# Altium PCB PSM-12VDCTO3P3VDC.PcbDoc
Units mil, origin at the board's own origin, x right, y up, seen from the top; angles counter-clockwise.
Board outline 8000 x 5800 mil, 2 copper layers (Top Layer, Bottom Layer), stack 62 mil thick; 35 components, 17 nets, 92 pads, 15 vias.
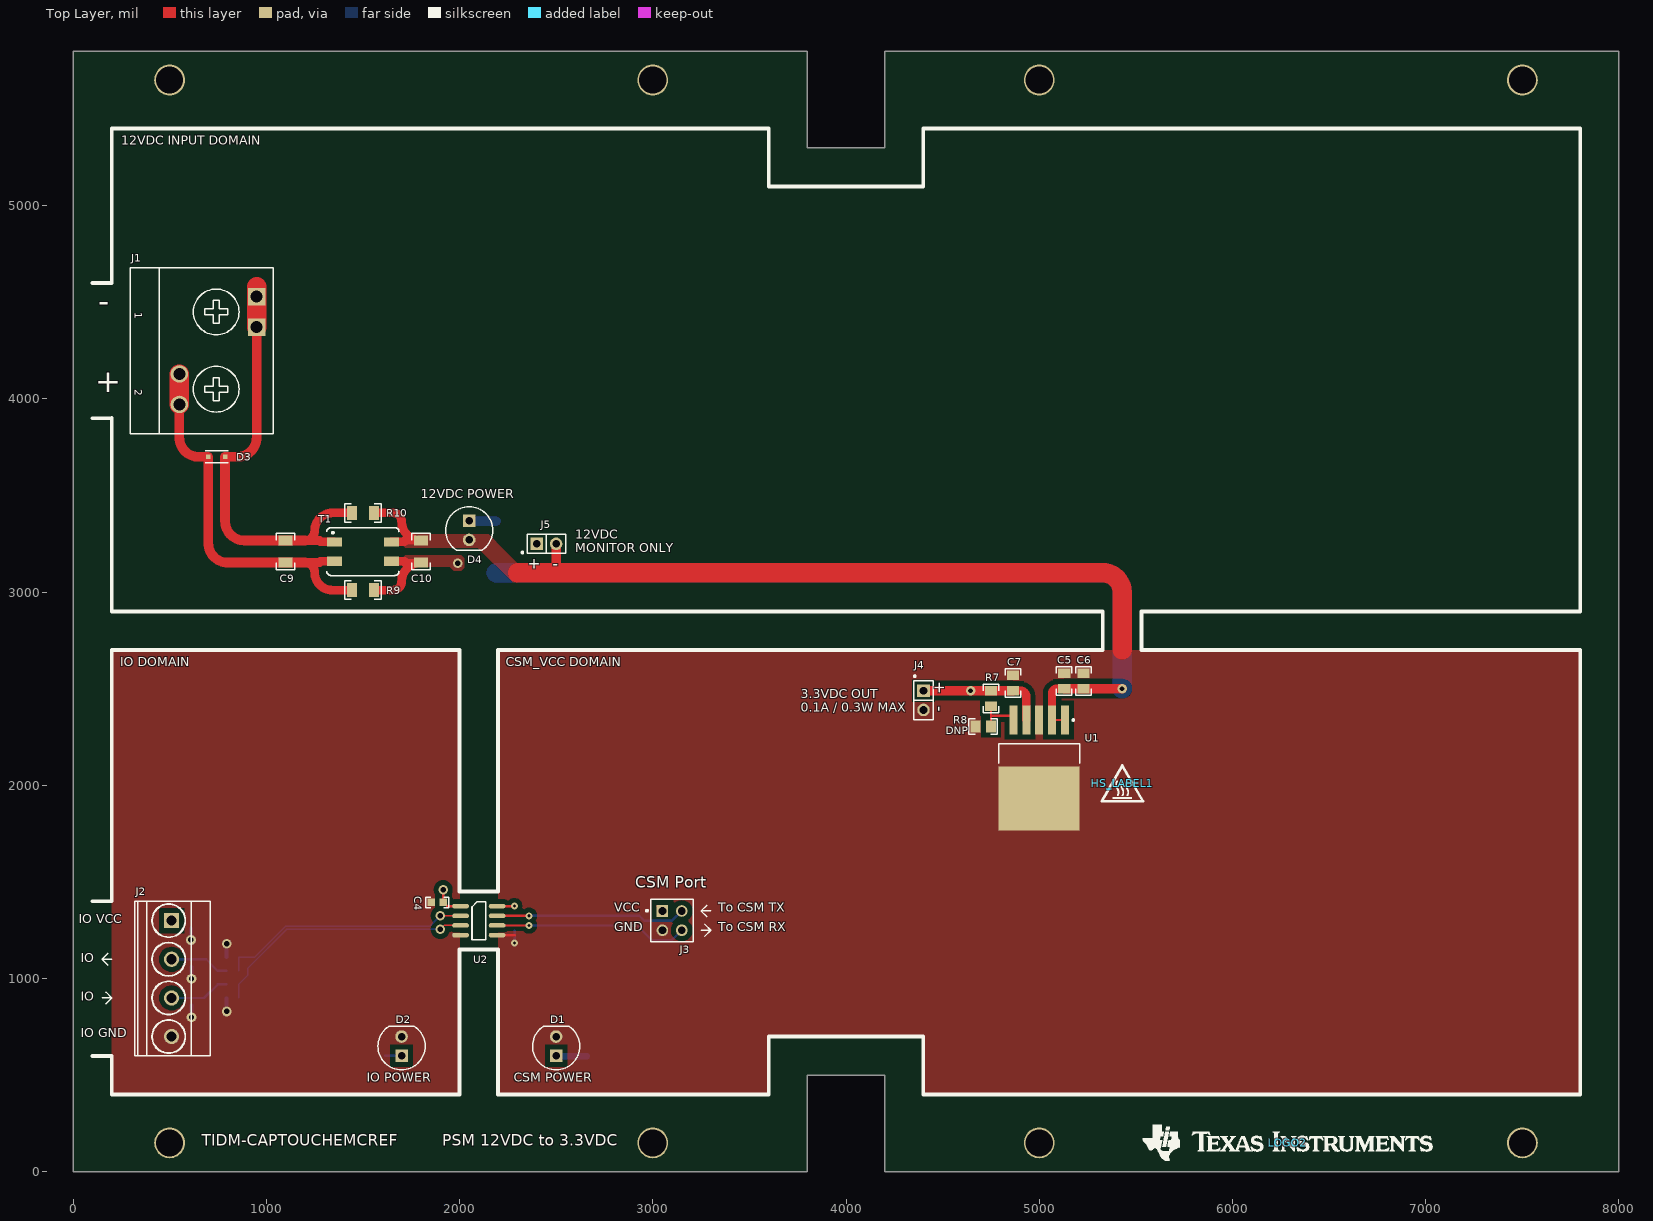
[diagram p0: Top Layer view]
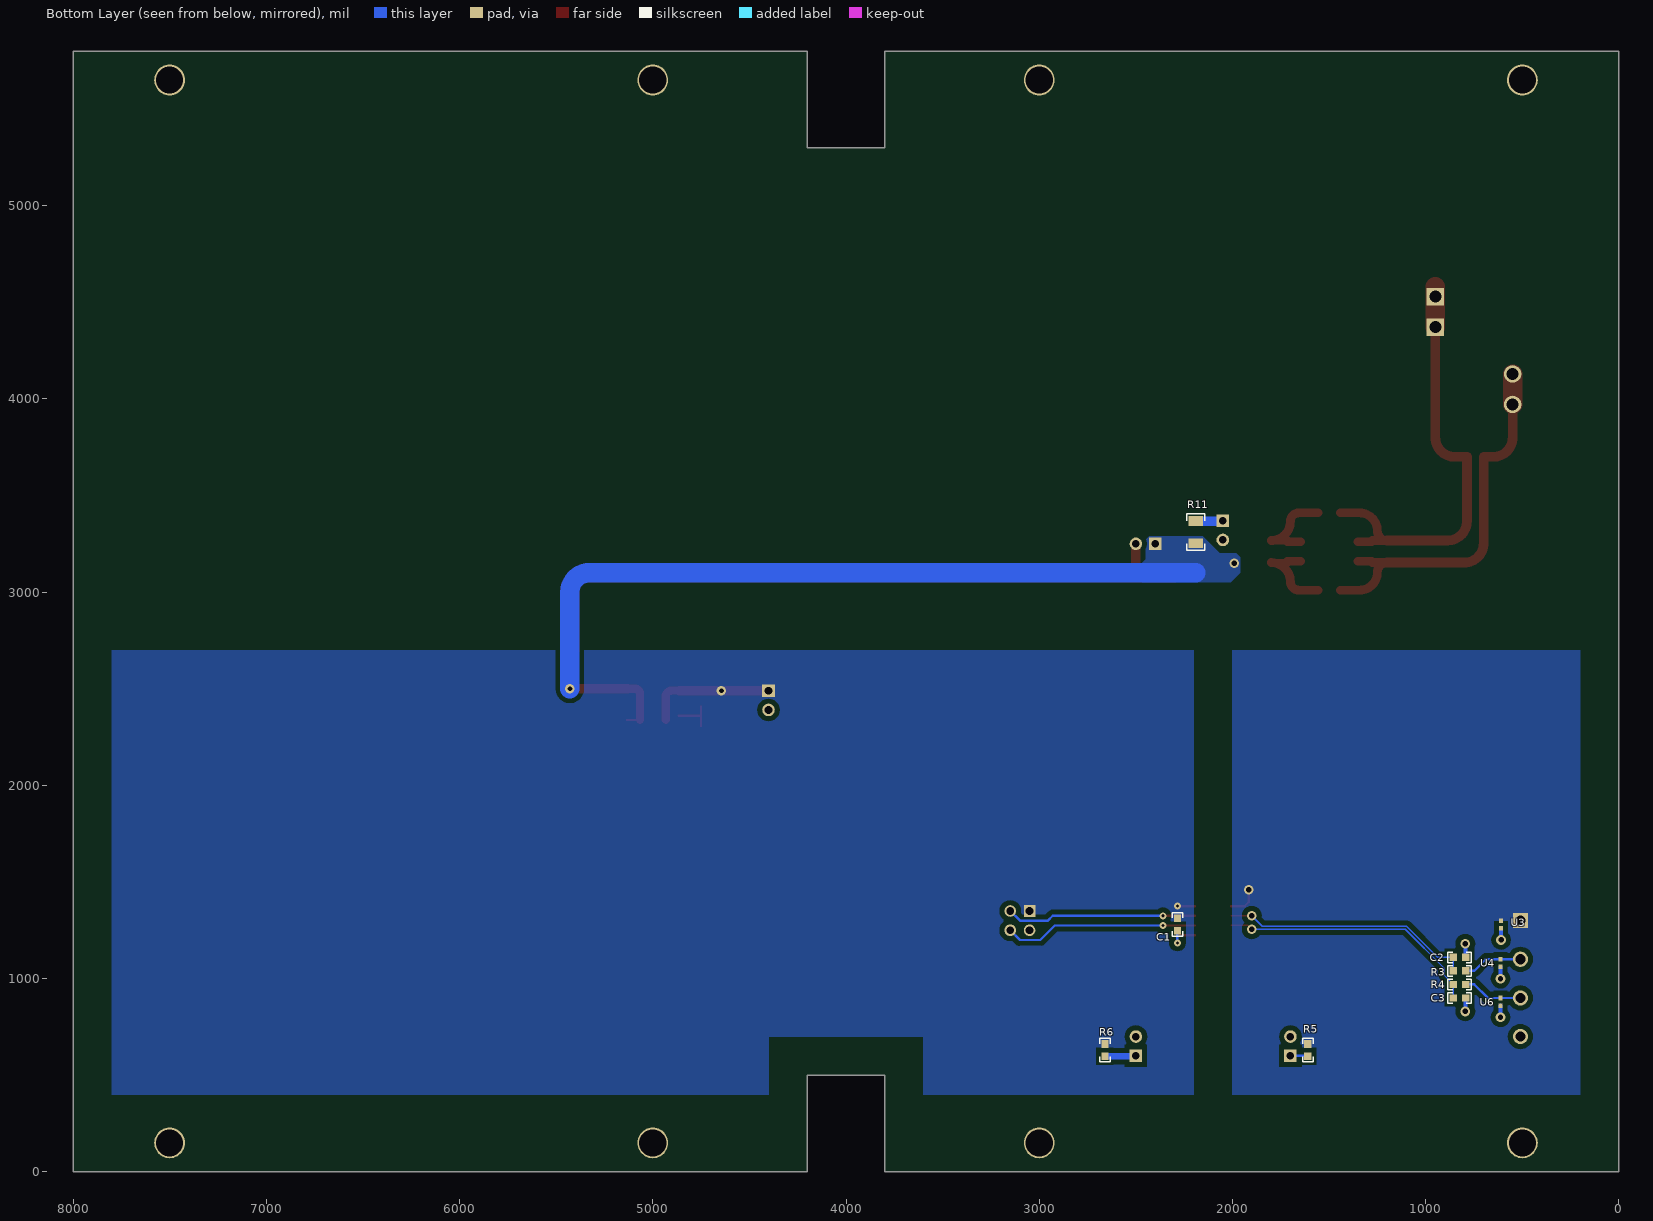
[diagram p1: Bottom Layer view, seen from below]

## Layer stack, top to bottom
Top Solder: solder mask 0.4, Solder Resist, Dk 3.5
Top Layer: signal copper 1.4
Dielectric1: core 59.2, FR-4, Dk 4.8
Bottom Layer: signal copper 1.4
Bottom Solder: solder mask 0.4, Solder Resist, Dk 3.5

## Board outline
0,0 0,5800 3800,5800 3800,5300 4200,5300 4200,5800 8000,5800 8000,0 4200,0 4200,500 3800,500 3800,0

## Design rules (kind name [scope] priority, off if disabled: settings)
AcuteAngle [All] p1: minimum=4.50000000000000E+0001 checktracksonly=FALSE
AssemblyTestPointUsage [All] p1: valid=2
Clearance Clearance_Keepouts [((IsTrack Or IsArc) And Not InPoly) And IsFree and IsKeepOut vs ((IsTrack Or IsArc) And Not InPoly) And IsFree and IsKeepOut] p1: gap=0
Clearance Clearance_BoardEdge_MountingHoles [OnCopper and InComponentClass('Mounting Holes') vs IsKeepOut] p2: gap=40
Clearance Clearance_BoardEdge_Poly [OnCopper and InPoly vs IsKeepOut] p3: gap=25
Clearance Clearance_BoardEdge [OnCopper and Not InComponentClass('Logo') and not InComponentClass('FiducialMark') and not InRegion(1000,500,4000,800) and Not IsKeepout vs IsKeepOut] p4: gap=75
Clearance Clearance_Poly [InPolygon] p5: gap=25
Clearance [All] p6: gap=7.87
ComponentClearance ComponentClearance_MountingHoles_FiducialMarks [InComponentClass('Mounting Holes') vs InComponentClass('FiducialMark')] p1: gap=50 collisioncheckmode=3 verticalgap=10 showdistances=FALSE
ComponentClearance ComponentClearance_Shunt [InComponentClass('Header') vs InComponentClass('Shunt')] p2: gap=0 collisioncheckmode=3 verticalgap=0 showdistances=FALSE
ComponentClearance ComponentClearance_Logo [InComponentClass('Logo')] p3: gap=50 collisioncheckmode=3 verticalgap=10 showdistances=FALSE
ComponentClearance ComponentClearance_ScrewToNut [(HasFootprint('NY PMS 440 0025 PH')) vs (HasFootprint('Keystone_1902C'))] p4: gap=5 collisioncheckmode=3 verticalgap=10 showdistances=FALSE
ComponentClearance ComponentClearance_MountingHoles [InComponentClass('Mounting Holes')] p5: gap=250 collisioncheckmode=3 verticalgap=100000 showdistances=FALSE
ComponentClearance ComponentClearance_SmallPassives [HasFootprint('0201*') or HasFootprint('0402*') or HasFootprint('0508') or HasFootprint('0603*') or HasFootprint('0612') or HasFootprint('0805*') or HasFootprint('0815*') or HasFootprint('0830*') or HasFootprint('1206*') or HasFootprint('1210*') or HasFootprint('1808*') or HasFootprint('1812*') or HasFootprint('1825*') or HasFootprint('2010*') or HasFootprint('2220*') or HasFootprint('2225*') or HasFootprint('2512*') or HasFootprint('2728*') or HasFootprint('3518*') vs HasFootprint('0201*') or HasFootprint('0402*') or HasFootprint('0508') or HasFootprint('0603*') or HasFootprint('0612') or HasFootprint('0805*') or HasFootprint('0815*') or HasFootprint('0830*') or HasFootprint('1206*') or HasFootprint('1210*') or HasFootprint('1808*') or HasFootprint('1812*') or HasFootprint('1825*') or HasFootprint('2010*') or HasFootprint('2220*') or HasFootprint('2225*') or HasFootprint('2512*') or HasFootprint('2728*') or HasFootprint('3518*')] p6: gap=20 collisioncheckmode=3 verticalgap=10 showdistances=FALSE
ComponentClearance ComponentClearance_THtoSMT [IsThruComponent vs IsSMTComponent] p7: gap=25 collisioncheckmode=3 verticalgap=30 showdistances=FALSE
ComponentClearance ComponentClearance_THtoTH [IsThruComponent vs IsThruComponent] p8: gap=50 collisioncheckmode=3 verticalgap=30 showdistances=FALSE
ComponentClearance [All] p9: gap=40 collisioncheckmode=3 verticalgap=10 showdistances=FALSE
DiffPairsRouting [All] p1: maxlimit=100 minlimit=10 mostfreqgap=10 toplayer_minwidth=15 toplayer_maxwidth=15 toplayer_prefwidth=15 bottomlayer_minwidth=15 bottomlayer_maxwidth=15 bottomlayer_prefwidth=15 maxuncoupledlength=1000
FabricationTestPointUsage TestPointUsage [All] p1: valid=2 allowmultiple=FALSE
FabricationTestpoint Testpoint [All] p1: side=3 testpointundercomponent=TRUE minsize=40 maxsize=100 preferedsize=60 minholesize=0 maxholesize=40 preferedholesize=32 testpointgrid=1 allowsidetop=TRUE allowsidebottom=TRUE usegrid=TRUE gridtolerance=0.01
FanoutControl Fanout_LCC [IsLCC] p1: bgadir=Out bgaviamode=Centered fanoutstyle=Auto fanoutdirection=Alternating viagrid=1 // Fanout_LCC (Default Rule)
FanoutControl Fanout_BGA [IsBGA] p2: bgadir=Out bgaviamode=Centered fanoutstyle=Auto fanoutdirection=Alternating viagrid=1 // Fanout_BGA (Default Rule)
FanoutControl Fanout_Default [All] p4: bgadir=Out bgaviamode=Centered fanoutstyle=Auto fanoutdirection=Alternating viagrid=1 // Fanout_Default (Default Rule)
FanoutControl Fanout_Small [(CompPinCount < 5)] p5: bgadir=Out bgaviamode=Centered fanoutstyle=Auto fanoutdirection=OutThenIn viagrid=1 // Fanout_Small (Default Rule)
Height [All] p1: minheight=0 maxheight=1500 prefheight=500
HoleSize [All] p1: absolutevalues=TRUE maxlimit=251 minlimit=8 maxpercent=80.000 minpercent=20.000
MinimumAnnularRing MinimumAnnularRing_ThermalPadVias [IsVia and InAnyComponent] p1: minimumring=5.91
MinimumAnnularRing [All] p2: minimumring=8
MinimumSolderMaskSliver MinimumSolderMaskSliver_Logo [InComponentClass('Logo') vs InComponentClass('Logo')] p1: minsoldermaskwidth=0.7
MinimumSolderMaskSliver [All] p2: minsoldermaskwidth=3.94
PlaneConnect [All] p1: planeconnectstyle=Relief reliefexpansion=10 reliefentries=4 reliefconductorwidth=10 reliefairgap=10
PolygonConnect [All] p1: connectstyle=Direct reliefconductorwidth=10 reliefentries=4 polygonreliefangle="90 Angle" airgapwidth=10
RoutingVias ThermalPadVias [IsVia and InAnyComponent] p1: holewidth=7.87 width=19.68 viastyle="Through Hole" minholewidth=7.87 minwidth=19.68 maxholewidth=12.99 maxwidth=23.62
RoutingVias [All] p2: holewidth=16 width=34 viastyle="Through Hole" minholewidth=7.87 minwidth=26 maxholewidth=40 maxwidth=65
SilkToBoardRegionClearance [Not ((IsComment or IsDesignator) And (Hide <> 'False')) and not InRegion(1000,500,4000,800)] p1:
SilkToSilkClearance SilkToSilkClearance_Pb-FreeLogo [(HasFootprint('Pb-Free_Overlay_Medium') OR HasFootprint('Pb-Free_Overlay_Small')) vs (HasFootprint('Pb-Free_Overlay_Medium') OR HasFootprint('Pb-Free_Overlay_Small'))] p1: silktosilkclearance=0
SilkToSilkClearance [All] p2: silktosilkclearance=5
SilkToSolderMaskClearance "Silk to Solder Mask Opening" [All] p1: minsilkscreentomaskgap=1 clearancetoexposedcopper=FALSE
SolderMaskExpansion [All] p1: expansion=3
Width [All] p1: maxlimit=100 minlimit=6 preferedwidth=10 checkconnectedcopper=TRUE
14 further rules are at their usual default settings.

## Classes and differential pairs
component class Header: J3 J4 J5
component class Logo: LOGO2

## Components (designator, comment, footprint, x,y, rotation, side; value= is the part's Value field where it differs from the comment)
C1 "GRM188R71C104KA01D" 0603 2285,1280 r270 bottom
C2 "06031C102JAT2A" 0603 825,1110 r180 bottom
C3 "06031C102JAT2A" 0603 825,900 r180 bottom
C4 "GRM188R71C104KA01D" 0603 1885,1395 r180 top
C5 "C2012X5R1E106K125AB" 0805_HV 5129,2540 r90 top
C6 "08053C104KAT2A" 0805_HV 5229,2540 r90 top
C7 "C2012X5R1C226K125AC" 0805_HV 4864,2530 r90 top
C9 "12061C104KAT2A" 1206 1100,3210 r90 top
C10 "12063C105KAT2A" 1206 1800,3210 r90 top
D1 "HLMP-3519" HLMP-351_GREEN 2500,650 r90 top
D2 "HLMP-3519" HLMP-351_GREEN 1700,650 r90 top
D3 "CDSOD323-T15SC" SOD-323-Bi 743.31,3700.01 r180 top
D4 "HLMP-3519" HLMP-351_GREEN 2050,3320 r270 top
HS_LABEL1 "CAUTION HOT SURFACE" IEC_HotSurface_Small 5430,2010 r0 top
J1 "0399100102" CONN_399100102 750,4250 r270 top
J2 "39544-3004" MOLEX_39544-3004 510,1000 r270 top
J3 "PEC02DAAN" Sullins_PEC02DAAN 3100,1300 r0 top
J4 "HTSW-102-07-G-S" Samtec_HTSW-102-07-G-S 4401.01,2440.21 r270 top
J5 "HTSW-102-07-G-S" Samtec_HTSW-102-07-G-S 2450,3250 r0 top
LOGO2 "Texas Instruments" TI_Horizontal_Overlay_Medium 6285,150 r0 top
R3 "CRCW060351R0JNEA" 0603 825,1040 r0 bottom
R4 "CRCW060351R0JNEA" 0603 825,970 r0 bottom
R5 "CRCW0603120RJNEA" 0603 1610,630 r90 bottom
R6 "CRCW0603120RJNEA" 0603 2660,630 r90 bottom
R7 "CRCW08050000Z0EA" 0805_HV 4750,2450 r90 top
R8 "CRCW08050000Z0EA" 0805_HV 4710,2305 r0 top
R9 "CRCW12060000Z0EA" 1206 1500,3010 r0 top
R10 "CRCW12060000Z0EA" 1206 1500,3410 r0 top
R11 "CRCW12061K00JNEA" 1206 2190,3310 r270 bottom
T1 "SRF0905-472Y" SRF0905 1500,3210 r0 top
U1 "TPS7A4533KTTR" KTT0005A_N 5000,2090 r270 top
U2 "ISO7221CD" D0008A_N 2100,1300 r0 top
U3 "TPD1E10B06DPYR" DPY0002A 610,1280 r90 bottom
U4 "TPD1E10B06DPYR" DPY0002A 612.76,1080 r90 bottom
U6 "TPD1E10B06DPYR" DPY0002A 612.76,880 r90 bottom

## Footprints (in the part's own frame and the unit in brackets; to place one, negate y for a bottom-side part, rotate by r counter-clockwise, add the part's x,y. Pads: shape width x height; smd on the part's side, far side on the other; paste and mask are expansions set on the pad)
0603 [mm] "0603 from SM-752 data"
  rect 1x0.95 smd: 1(-0.8,0) 2(0.8,0)
  silkscreen extent -1.52,-0.69 1.52,0.69, body extent -0.87,-0.47 0.87,0.47, height 0.85
0805_HV [mil] "0805 with 30mil clearance between pads"
  rect 50x63 smd: 1(-40,0) 2(40,0)
  silkscreen extent -74,-40 74,40, body extent -43,-29 43,29, height 43
1206 [mm] "1206 from SM-752 data"
  rect 1.3x1.85 smd: 1(-1.45,0) 2(1.45,0)
  silkscreen extent -2.4,-1.21 2.4,1.21, body extent -1.7,-0.9 1.7,0.9, height 1.35
CONN_399100102 [mm] "Molex"
  rect 2.3x2.3 hole 1.587: 1(-7.085,5.08) 1A(-3.075,5.08)
  round 2.3 hole 1.587: 2(3.075,-5.08) 2A(7.085,-5.08)
  silkscreen extent -10.88,-11.53 10.96,7.27, body extent -10.88,-11.53 10.96,7.27, height 31.1
D0008A_N [mm] "SOIC, 8-Leads, Body 4.9x3.9mm, Pitch 1.27mm, IPC Medium Density"
  oval 2.2x0.6 smd: 1(-2.4,1.905) 2(-2.4,0.635) 3(-2.4,-0.635) 4(-2.4,-1.905) 5(2.4,-1.905) 6(2.4,-0.635) 7(2.4,0.635) 8(2.4,1.905)
  silkscreen extent -0.9,-2.5 0.9,2.5, body extent -3,-2.45 3,2.45, height 1.63
DPY0002A [mm] "R-PX2SON-N2"
  rect 0.6x0.5 smd: 1(-0.5,0) 2(0.5,0)
  body extent -0.55,-0.35 0.55,0.35, height 0.4
HLMP-351_GREEN [mm] "AVAGO"
  rect 1.65x1.65 hole 1: 1(-1.27,0)
  round 1.65 hole 1: 2(1.27,0)
  silkscreen extent -3.1,-3.1 2.6,3.1, body extent -3.05,-3.06 2.57,3.06, height 10.78
IEC_HotSurface_Small [mil]
  silkscreen extent -107,-93 107,92
KTT0005A_N [mm] "D2-PAK, 6-Leads, Body 8.9x10.2mm, Pitch 1.7mm, Lead Span 15.2mm, IPC Medium Density"
  rect 3.8x1.05 smd: 1(-6.3,3.4) 2(-6.3,1.7) 3(-6.3,0) 4(-6.3,-1.7) 5(-6.3,-3.4)
  rect 8.4x10.65 smd: 6(4,0)
  silkscreen extent -6.42,-5.35 -0.65,5.35, body extent -3.2,-5.32 6.45,5.33, height 4.83
MOLEX_39544-3004 [mm] "Molex"
  rect 2x2 hole 1.321: 1(-7.62,0)
  round 2 hole 1.321: 2(-2.54,0) 3(2.54,0) 4(7.62,0)
  silkscreen extent -10.16,-4.83 10.16,5.08, body extent -10.16,-4.83 10.16,5.08, height 14.49
Samtec_HTSW-102-07-G-S [mm] "Samtec 100mil, 1x2, 230 mil above insulator"
  rect 1.65x1.65 hole 1.016 mask+0: 1(-1.27,0)
  round 1.65 hole 1.016 mask+0: 2(1.27,0)
  silkscreen extent -3.3,-1.27 2.54,1.27, body extent -2.54,-1.27 2.54,1.27, height 8.38
SOD-323-Bi [mm] "SOD323, 2-Leads, Body 1.9x1.45mm, No Polarity Mark"
  rect 0.6x0.6 smd paste-0.05: 1(-1.1,0) 2(1.1,0)
  silkscreen extent -1.53,-0.77 1.53,0.77, body extent -1.27,-0.65 1.27,0.65, height 1.02
SRF0905 [mm] "Bourns SRF0905 series recommended land pattern"
  rect 2x1.2 smd: 1(-3.75,1.27) 2(-3.75,-1.27) 3(3.75,-1.27) 4(3.75,1.27)
  silkscreen extent -4.75,-3.15 4.75,3.15, body extent -4.75,-3.15 4.75,3.15, height 5.3
Sullins_PEC02DAAN [mil] "Sullins Connector Solutions"
  rect 60x60 hole 40: 1(-50,50)
  round 60 hole 40: 2(50,50) 3(-50,-50) 4(50,-50)
  silkscreen extent -134,-110 110,110, body extent -110,-110 110,110, height 310
TI_Horizontal_Overlay_Medium [mil]
  silkscreen extent -750,-94 750,94

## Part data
C1 C4: "CAP, CERM, 0.1 µF, 16 V, +/- 10%, X7R, 0603"
C2 C3: "CAP, CERM, 1000 pF, 100 V, +/- 5%, X7R, 0603"
C5: "CAP, CERM, 10 µF, 25 V, +/- 10%, X5R, 0805"
C6: "CAP, CERM, 0.1 µF, 25 V, +/- 10%, X7R, 0805"
C7: "CAP, CERM, 22 µF, 16 V, +/- 10%, X5R, 0805"
C9: "CAP, CERM, 0.1 µF, 100 V, +/- 10%, X7R, 1206"
C10: "CAP, CERM, 1 µF, 25 V, +/- 10%, X7R, 1206"
D1 D2 D4: "LED, Green, TH"
D3: "Diode, TVS, Bi, 15 V, 400 W, SOD323, 2-Leads, Body 1.9x1.45mm, No Polarity Mark"
HS_LABEL1: library part IEC_HotSurface, "IEC 61010-1 Hot Surface Warning"
J1: "Terminal Block, 60A, 10.16mm Pitch, 2-Pos, TH"
J2: "Terminal Block, 4x1, 5.08mm, TH"
J3: "Header, 100mil, 2x2, Tin, TH"
J4 J5: "Header, 100mil, 2x1, Gold, TH"
LOGO2: library part TI_Logo, "Texas Instrument Corporate Signature"
R3 R4: "RES, 51, 5%, 0.1 W, 0603"
R5 R6: "RES, 120, 5%, 0.1 W, 0603"
R7 R8: "RES, 0 ohm, 5%, 0.125W, 0805"
R9 R10: "RES, 0, 5%, 0.25 W, 1206"
R11: "RES, 1.0 k, 5%, 0.25 W, 1206"
T1: "Line Filter"
U1: "Single Output Fast Transient Response LDO, 1.5 A, Fixed 3.3 V Output, 2.1 to 20 V Input, 5-pin DDPAK (KTT), -40 to 125 degC, Green (RoHS & no Sb/Br)"
U2: "25 Mbps Dual Channels, 1 / 1, Digital Isolator, 3.3 V / 5 V, -40 to +125 degC, 8-pin SOIC (D), Green (RoHS & no Sb/Br)"
U3 U4 U6: "ESD in 0402 Package with 10 pF Capacitance and 6 V Breakdown, 1 Channel, -40 to +125 degC, 2-pin X2SON (DPY), Green (RoHS & no Sb/Br)"

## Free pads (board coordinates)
  round 160 hole 140: 0(500,150) 0(500,5650) 0(3000,150) 0(3000,5650) 0(5000,150) 0(5000,5650) 0(7500,150) 0(7500,5650)

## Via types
v1: diameter 50, hole 28, Top Layer to Bottom Layer, 9 vias
v2: diameter 36, hole 16, Top Layer to Bottom Layer, 4 vias
v3: diameter 50, hole 25, Top Layer to Bottom Layer, 2 vias

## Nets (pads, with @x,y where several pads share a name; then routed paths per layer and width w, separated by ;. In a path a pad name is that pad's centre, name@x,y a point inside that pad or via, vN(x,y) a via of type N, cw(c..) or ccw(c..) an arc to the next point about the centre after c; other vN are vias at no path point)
CSM_RXD: J3.4 U2.6 | length 1007.3
  Top Layer w12: U2.6 v2(2360,1275)
  Bottom Layer w12: v2(2360,1275) 2920,1275 2995,1200 3100,1200 J3.4
CSM_TXD: J3.2 U2.7 | length 986.6
  Top Layer w12: U2.7 v2(2360,1325)
  Bottom Layer w12: v2(2360,1325) 2930,1325 2955,1300 3100,1300 J3.2
CSM_VCC: C1.1 C7.1 J3.1 J4.1 R6.2 R7.2 U1.4 U2.8 | length 795.7
  Top Layer w12: U2.8 v2(2283.5,1375) ; J3.1@3025,1375 J3.1
  Top Layer w42: C7.1 4904,2490 cw(c4904,2460.93) 4933.07,2460.93 U1.4
  Top Layer w50: J4.1@4401.22,2490 v3(4645,2490) R7.2 C7.1
GND: C1.2 C5.2 C6.2 C7.2 C10.2 D1.2 D4.2 J3.3 J4.2 J5.2 R8.1 R10.2 T1.4 U1.3 U1.6 U2.5 | length 4197.2
  Top Layer w12: U2.5@2195.98,1225 2285,1225
  Top Layer w45: R10.2 1657.09,3410 cw(c1657.09,3367.09) 1700,3367.09 ccw(c1800,3367.09) C10.2@1776.04,3270 ; T1.4 1710,3260 ccw(c1710,3270) 1720,3270 C10.2@1776.04,3270 ; C10.2 cw(c1800,3367.09) C10.2@1776.04,3270
  Top Layer w50: 2500,3150 J5.2
  Top Layer w100: 2300,3100 5329,3100 cw(c5329,3000) 5429,3000 5429,2700
  Bottom Layer w12: v2(2285,1185) C1.2
IO_GND: C2.2 C3.2 C4.2 D2.2 J2.4 U2.4 U3.1 U4.1 U6.1 | length 318
  Bottom Layer w20: v1(610,1200) U3.1 ; v1(612.76,800) U6.1 ; v1(612.76,1000) U4.1 ; v1(795,830) C3.2@795,898.5 ; C2.2@795,1111.5 v1(795,1180)
IO_RXD: J2.3 R4.1 U6.2 | length 312.3
  Bottom Layer w12: J2.3 U6.2@612.45,900 ; U6.2 678.19,899.68 748.5,970 R4.1
IO_TXD: J2.2 R3.1 U4.2 | length 308.5
  Bottom Layer w12: J2.2 612.76,1100 U4.2 688.82,1099.68 748.5,1040 R3.1
IO_VCC: C4.1 J2.1 R5.2 U2.1 U3.2 | length 160.8
  Top Layer w12: v1@1916.5,1458.5 C4.1 1936.5,1375 U2.1
  other v1: 1915,1460
NetC2_1: C2.1 R3.2 U2.2 | length 1314.3
  Top Layer w8: v1@1900,1340 1915,1325 U2.2
  Bottom Layer w8: R3.2 C2.1 938.43,1110 1099.3,1270.87 1845.87,1270.87 v1(1900,1325)
NetC3_1: C3.1 R4.2 U2.3 | length 1366.2
  Top Layer w8: v1(1900,1255) 1920,1275 U2.3
  Bottom Layer w8: C3.1 R4.2 905,1018.5 905,1054.13 1105.87,1255 v1(1900,1255)
NetD1_1: D1.1 R6.1 | length 161.5
  Bottom Layer w32: D1.1@2498.5,598.5 R6.1
NetD2_1: D2.1 R5.1 | length 84.3
  Bottom Layer w12: R5.1@1615.71,600 D2.1
NetD4_1: D4.1 R11.1 | length 137.1
  Bottom Layer w50: D4.1@2052.91,3367.09 R11.1
NetR7_1: R7.1 R8.2 U1.5 | length 220
  Top Layer w12: R8.2 4750,2360 ; R7.1 4750,2360 ; U1.5@4865,2360 4750,2360
TERMINAL_L: C9.1 D3.2 J1.2 J1.2A R9.1 T1.2 | length 2021.1
  Top Layer w45: T1.2 1280,3160 cw(c1272.91,3160) 1272.91,3152.91 1200,3152.91 cw(c1200,3102.91) 1250,3102.91 ccw(c1342.91,3102.91) 1342.91,3010 R9.1
  Top Layer w50: J1.2A 550,3800 ccw(c650,3800) 650,3700 D3.2 700,3252.91 ccw(c800,3252.91) 800,3152.91 C9.1 1200,3152.91
  Top Layer w100: J1.2A J1.2
TERMINAL_N: C9.2 D3.1 J1.1 J1.1A R10.1 T1.1 | length 2284.7
  Top Layer w45: T1.1 1280,3260 ccw(c1272.91,3260) 1272.91,3267.09 1200,3267.09 ccw(c1200,3317.09) 1250,3317.09 cw(c1342.91,3317.09) 1342.91,3410 R10.1
  Top Layer w50: J1.1A 950,3800 cw(c850,3800) 850,3700 D3.1 786.62,3367.09 ccw(c886.62,3367.09) 886.62,3267.09 C9.2 1200,3267.09
  Top Layer w100: J1.1A J1.1 950,4580
TERMINAL_VCC: C5.1 C6.1 C10.1 J5.1 R9.2 R11.2 T1.3 U1.1 U1.2 | length 4836.2
  Top Layer w12: U1.2 U1.1
  Top Layer w42: U1.2 5066.93,2477.93 cw(c5089,2477.93) 5089,2500 C5.1
  Top Layer w45: R9.2 1657.09,3010 ccw(c1657.09,3052.91) 1700,3052.91 cw(c1800,3052.91) C10.1@1776.04,3150 ; T1.3 1710,3160 cw(c1710,3150) 1720,3150 C10.1@1776.04,3150 ; C10.1 ccw(c1800,3052.91) C10.1@1776.04,3150
  Top Layer w50: C5.1 C6.1 v3(5429,2500)
  Bottom Layer w100: 2190,3100 5329,3100 cw(c5329,3000) 5429,3000 v3(5429,2500)
  other v1: 1990,3150

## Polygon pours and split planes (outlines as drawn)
TERMINAL_VCC on Bottom Layer "Bottom Layer-No Net 3" (solid, remove dead copper, pour order 14): 2300,3290 2430,3290 2450,3270 2450,3230 2450,3170 2470,3150 2470,3060 2480,3050 2010,3050 1960,3100 1960,3180 1980,3200 2060,3200 2064.57,3200 2154.57,3290 2330,3290
CSM_VCC on Bottom Layer "Bottom Layer-No Net 1" (solid, remove dead copper, pour order 12): 2200,2700 2200,400 3600,400 3600,700 4400,700 4400,400 7800,400 7800,2700 2200,2700
IO_VCC on Bottom Layer "IO_VCC_L02_P023" (solid, remove dead copper, pour order 23): 200,2700 2000,2700 2000,400 200,400 200,2690
TERMINAL_VCC on Top Layer "Top Layer-No Net 9" (solid, remove dead copper, pour order 19): 1710,3180 1720,3190 2010,3190 2025,3175 2025,3125 2010,3110 1970,3110 1955,3125 1950,3130 1710,3130 1710,3180
GND on Top Layer "Top Layer-No Net 6" (solid, remove dead copper, pour order 17): 1710,3240 1720,3230 1940,3230 2095,3230 2275,3050 2300,3050 2300,3150 2230,3220 2150,3300 1710,3300 1710,3240
GND on Top Layer "Top Layer-No Net" (solid, remove dead copper, pour order 13): 2200,2700 2200,400 3600,400 3600,685.21 cw(c3614.79,685.21) 3614.79,700 4400,700 4400,400 7800,400 7800,2700 2200,2700
IO_GND on Top Layer "IO_GND_L01_P025" (solid, remove dead copper, pour order 25): 200,2700 2000,2700 2000,400 200,400 200,2700

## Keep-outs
Keep-Out Layer:
  text ".Layer_Name" at 577,-858.49 h60

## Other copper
Top Layer:
  text ".Layer_Name" at 577,-858.49 h60
Bottom Layer:
  text ".Layer_Name" at 577,-858.49 h60

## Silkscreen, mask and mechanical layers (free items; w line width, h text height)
Top Overlay:
  lines w7.87: 150,900 200,900 ; 170,870 200,900 ; 170,930 200,900 ; 180,1070 150,1100 ; 180,1130 150,1100 ; 200,1100 150,1100 ; 3250,1250 3300,1250 ; 3270,1220 3300,1250 ; 3270,1280 3300,1250 ; 3280,1320 3250,1350 ; 3280,1380 3250,1350 ; 3300,1350 3250,1350
  lines w20: 100,600 200,600 200,400 2000,400 2000,1150 2200,1150 2200,400 3600,400 3600,700 4400,700 4400,400 7800,400 7800,2700 5529,2700 5529,2800 5529,2900 7800,2900 7800,5400 4400,5400 4400,5100 3600,5100 3600,5400 200,5400 200,4600 100,4600 ; 100,1400 200,1400 200,2700 2000,2700 2000,1450 2200,1450 2200,2700 5329,2700 5329,2900 200,2900 200,3900.45 199.55,3900 100,3900
  text "12VDC INPUT DOMAIN" at 250,5300 h80
  text "-" at 130,4410 h200
  text "+" at 115,3995 h200
  text "12VDC POWER" at 1800,3470 h80
  text "12VDC" at 2600,3260 h80
  text "+" at 2420,3190 h100 r180
  text "MONITOR ONLY" at 2600,3190 h80
  text "-" at 2510,3183 h100 r180
  text "IO DOMAIN" at 245,2600 h80
  text "CSM_VCC DOMAIN" at 2240,2600 h80
  text "+" at 4530,2471 h100 r90
  text "3.3VDC OUT" at 3765,2435.96 h80
  text "-" at 4523,2380 h100 r90
  text "0.1A / 0.3W MAX" at 3765,2365.96 h80
  text "DNP" at 4515,2265 h40
  text "CSM Port" at 2910,1450 h100
  text "VCC" at 2800,1330 h80
  text "To CSM TX" at 3340,1330 h80
  text "IO VCC" at 30,1270 h80
  text "GND" at 2800,1230 h80
  text "To CSM RX" at 3340,1230 h80
  text "IO" at 40,1070 h80
  text "IO" at 40,870 h80
  text "IO GND" at 40,680 h80
  text "IO POWER" at 1520,450 h80
  text "CSM POWER" at 2280,450 h80
  text "TIDM-CAPTOUCHEMCREF" at 665,115 h100
  text "PSM 12VDC to 3.3VDC" at 1910,115 h100
  text ".Layer_Name" at 577,-858.49 h60
Bottom Overlay:
  text ".Layer_Name" at 577,-858.49 h60
Top Paste:
  text ".Layer_Name" at 577,-858.49 h60
Bottom Paste:
  text ".Layer_Name" at 577,-858.49 h60
Top Solder:
  text ".Layer_Name" at 577,-858.49 h60
  text ".Layer_Name" at 577,-858.49 h60
Bottom Solder:
  text ".Layer_Name" at 577,-858.49 h60
Drill Guide:
  text ".Layer_Name" at 577,-858.49 h60
M1 Board Outline:
  lines w19.68: 0,0 0,5800 3800,5800 3800,5300 4000,5300 4200,5300 4200,5800 8000,5800 8000,0 4200,0 4200,500 4000,500 3800,500 3800,0 0,0
  text ".Layer_Name" at 577,-858.49 h60
M2 Board Dimensions:
  rectangle: 125,-400 500,-275
  rectangle: 0,-275 125,-150
  lines w7: 0,-275 1000,-275 ; 125,-400 125,-150 ; 250,-400 250,-150 ; 500,-400 500,-150 ; 750,-400 750,-150 ; 0,-400 0,-150 1000,-150 1000,-400 0,-400
  text ".Layer_Name" at 577,-858.49 h60
M3 3D STEP Top:
  text ".Layer_Name" at 577,-858.49 h60
M4 3D STEP Bottom:
  text ".Layer_Name" at 577,-858.49 h60
M5 Assembly Top:
  lines w10: 3440,-726.83 3440,-523.5 ; -292,-1133.5 3713,-1133.5 ; -292,-1133.5 -292,-523.5 -292,-1133.5 ; -292,-1133.5 3713,-1133.5 ; -291.5,-1133.5 -291.5,-523.5 ; -291.5,-1133.5 1284,-1133.5 -291.5,-1133.5 ; -291.5,-1133.5 -291.5,-523.5 ; -291.5,-523.5 6310,-523.5 ; -291.5,-523.5 6310,-523.5 ; 3713,-1133.5 6310,-1133.5 ; 3713,-1133.5 6310,-1133.5 ; 6310,-1133.5 6310,-523.5 ; 6310,-1133.5 6310,-523.5 ; -292,-930.17 6308,-930.17 -292,-930.17 ; -292,-726.83 6310,-726.83 -292,-726.83 ; 2173,-1133.5 2173,-523.5 2173,-1133.5 ; 4280,-726.83 4280,-523.5 4280,-726.83 ; 4902,-1140 4902,-937.17 4902,-1140
  text "PCB VIEWED FROM TOP SIDE" at -228.5,-655.67 h60
  text "BOARD #:" at 2248,-655.67 h60
  text ".PRJ_Number" at 2793.5,-655.67 h60
  text "REV:" at 3638,-655.67 h60
  text ".PCB_Rev" at 3929.5,-655.67 h60
  text "SVN REV:" at 4476,-655.67 h60
  text "TID #:" at 2248,-859 h60
  text ".TID" at 2793.5,-859 h60
  text "PLOT NAME =" at -228.5,-1064.34 h60
  text ".plot_File_Name" at 577,-1064.34 h60
  text "GENERATED    :" at 2250,-1064.34 h60
  text ".Print_Date" at 3119.5,-1064.34 h60
  text ".Print_Time" at 3848.5,-1064.34 h60
  text "TEXAS INSTRUMENTS" at 5113,-1064.34 h60
M6 Assembly Bottom:
  lines w10: 1737.5,-727.33 1737.5,-524 ; 2577.5,-727.33 2577.5,-524 ; -292.5,-1134 2304.5,-1134 ; -292.5,-1134 -292.5,-524 ; -292.5,-1134 2304.5,-1134 ; -292.5,-1134 -292.5,-524 ; -292.5,-524 6309,-524 ; -292.5,-524 6309,-524 ; 2304.5,-1134 6309.5,-1134 ; 2304.5,-1134 6309.5,-1134 ; 6309,-1134 4733.5,-1134 6309,-1134 ; 6309,-1134 6309,-524 ; 6309,-1134 6309,-524 ; 6309.5,-1134 6309.5,-524 6309.5,-1134 ; -292.5,-727.33 6309.5,-727.33 -292.5,-727.33 ; -290.5,-930.67 6309.5,-930.67 -290.5,-930.67 ; 1115.5,-1140.5 1115.5,-937.67 1115.5,-1140.5 ; 3844.5,-1134 3844.5,-524 3844.5,-1134
  text ".VersionControl_RevNumber" at 1035.5,-656.17 h60
  text "SVN REV:" at 1541.5,-656.17 h60
  text ".PCB_Rev" at 2088,-656.17 h60
  text "REV:" at 2379.5,-656.17 h60
  text ".PRJ_Number" at 3224,-656.17 h60
  text "BOARD #:" at 3769.5,-656.17 h60
  text "PCB VIEWED FROM BOTTOM SIDE" at 6246,-656.17 h60
  text ".TID" at 3224,-859.5 h60
  text "TID #:" at 3769.5,-859.5 h60
  text "TEXAS INSTRUMENTS" at 904.5,-1064.84 h60
  text ".Print_Time" at 2169,-1064.84 h60
  text ".Print_Date" at 2898,-1064.84 h60
  text "GENERATED    :" at 3767.5,-1064.84 h60
  text ".plot_File_Name" at 5440.5,-1064.84 h60
  text "PLOT NAME =" at 6246,-1064.84 h60
M9 Title Sheet:
  drawing of 58 lines, arcs and shapes, not listed
  text "1" at 739.84,8036.5 h70
  text "2" at 3235.5,8036.5 h70
  text "3" at 5724.84,8036.5 h70
  text "4" at 8231.51,8036.5 h70
  text "5" at 10730.5,8036.5 h70
  text "6" at 13235.5,8036.5 h70
  text "A" at -416.5,6893.5 h70
  text "A" at 14383.5,6893.5 h70
  text "B" at -416.5,4513.5 h70
  text "B" at 14383.5,4513.5 h70
  text "C" at -416.5,2138.5 h70
  text "C" at 14383.5,2138.5 h70
  text "PROJECT TITLE:" at 11343.5,277.5 h45
  text "TIDM-CAPTOUCHEMCREF PSM 12V to 3.3V" at 11393.5,144.17 h70
  text "DESIGNED FOR:" at 11343.5,-23.5 h45
  text "TI Designs" at 11393.5,-163.5 h70
  text "D" at -416.5,-231.5 h70
  text "D" at 14383.5,-231.5 h70
  text "FILE NAME:" at 11343.5,-323.5 h45
  text ".PCB_File_Name_No_Path" at 11393.5,-443.5 h70
  text "Texas Instruments (TI) and/or its licensors do not warrant the accuracy or completeness of this specification" at 6374,-605.34 h45
  text "ENGINEER:" at 11343.5,-613.5 h45
  text "LAYOUT BY:" at 12848.5,-613.5 h45
  text "or any information contained therein. TI and/or its licensors do not warrant that this design will meet" at 6329.01,-718 h45
  text "W. Schnoor" at 11393.5,-768.49 h70
  text "W. Schnoor" at 12899,-768.49 h70
  text "the specifications, will be suitable for your application or fit for any particular purpose, or will operate in" at 6329.01,-830.67 h45
  text ".Layer_Name" at 577,-858.49 h60
  text "ALTIUM DESIGNER VERSION:" at 12848.5,-923.5 h45
  text "an implementation. TI and/or its licensors do not warrant that the design is production worthy. You should" at 6329.01,-943.33 h45
  text "completely validate and test your design implementation to confirm the system functionality for your application." at 6374,-1056 h45
  text ".print_Scale" at 11393.5,-1056.83 h70
  text ".Application_BuildNumber" at 12899,-1056.83 h70
  text "1" at 739.84,-1263.5 h70
  text "2" at 3235.5,-1263.5 h70
  text "3" at 5724.84,-1263.5 h70
  text "4" at 8231.51,-1263.5 h70
  text "5" at 10730.5,-1263.5 h70
  text "6" at 13235.5,-1263.5 h70
M10 Fab Notes:
  drawing of 185 lines, arcs and shapes, not listed
  text "DESIGN INFORMATION" at 12381.02,5910 h60
  text "MIN. TRACK WIDTH:" at 11736.46,5730 h60
  text "8" at 12832.7,5730 h60
  text "MIL" at 12987.46,5730 h60
  text "MIN. CLEARANCE:" at 11736.46,5598 h60
  text "0.2" at 12772.7,5598 h60
  text "mm" at 12987.46,5598 h60
  text "MIN. VIA PAD SIZE:" at 11736.46,5466 h60
  text "24" at 12802.71,5466 h60
  text "MIL" at 12987.46,5466 h60
  text "0.05mm (2MIL)" at 12431.46,5324.29 h60
  text "MINIMUM ANNULAR RING" at 11407.23,5320 h60
  text "EXTERNAL" at 13139.46,5320 h60
  text "PER" at 11607.23,5202 h60
  text "IPC-D-275 CLASS 2 LEVEL C" at 11827.23,5202 h60
  text "MIL, HOLES" at 13315.46,5089.71 h60
  text "+/-" at 12923,5089 h60
  text "+/-" at 13777,5089 h60
  text "REGISTRATION TOLERANCES:" at 11407.23,5084 h60
  text "METAL" at 12607,5084 h60
  text "5" at 13183.2,5084 h60
  text "3" at 14016.2,5084 h60
  text "MIL" at 14132.46,5084 h60
  text "MATERIAL:" at 11332.46,4874.54 h60
  text "FR-4 High Tg" at 12318.9,4734.21 h60
  text "FR-408" at 11753.46,4725.64 h60
  text "X" at 12165.46,4725.64 h60
  text "OTHER" at 13241.46,4725.64 h60
  text "62 MIL (1.6mm) +/-10%" at 12073.56,4562.92 h60
  text "THICKNESS:" at 11407.23,4558.64 h60
  text "X" at 11945.4,4558.64 h60
  text "OTHER" at 13358.46,4558.64 h60
  text "TOLERANCE:" at 11407.23,4400.64 h60
  text "X" at 12246.53,4400.64 h60
  text "ANSI IPC-6012 TYPE 3 CLASS 2" at 12433.48,4400.64 h60
  text "OTHER +/-" at 12433.46,4244.64 h60
  text "BOW & TWIST:" at 11407.23,4087.64 h60
  text "X" at 12246.53,4087.64 h60
  text "ANSI IPC-6012 TYPE 3 CLASS 2" at 12433.48,4087.64 h60
  text "OTHER +/-" at 12433.46,3929.13 h60
  text "DRILLING:" at 11332.46,3790.64 h60
  text "REFERENCE:" at 11407.23,3673.64 h60
  text "X" at 12055.46,3673.64 h60
  text "AS SHOWN" at 12242.46,3673.64 h60
  text "X" at 12956.46,3673.64 h60
  text "NC_DRILL FILES" at 13093.46,3673.64 h60
  text "PTH MIN COPPER THICKNESS:" at 11407.23,3515.64 h60
  text "X" at 12757.46,3515.64 h60
  text "1MIL" at 12894.46,3515.64 h60
  text "OTHER" at 13391.46,3515.64 h60
  text "BOARD FINISH:" at 11332.46,3356.64 h60
  text "SILKSCREEN:" at 11487.68,3238.64 h60
  text "X" at 12436.46,3238.64 h60
  text "TOP" at 12562.46,3238.64 h60
  text "X" at 12946.46,3238.64 h60
  text "BOTTOM" at 13073.46,3238.64 h60
  text "SILKSCREEN COLOR:" at 11487.68,3071.64 h60
  text "X" at 12435.42,3071.64 h60
  text "WHITE" at 12562.46,3071.64 h60
  text "OTHER" at 13073.46,3071.64 h60
  text "SOLDER RESIST COLOR:" at 11487.68,2901.64 h60
  text "X" at 12055.42,2742.44 h60
  text "GREEN" at 12182.46,2742.44 h60
  text "BLUE" at 12773.46,2742.44 h60
  text "OTHER" at 13311.46,2742.44 h60
  text "IMMERSION GOLD (ENIG)" at 12393.46,2553.92 h60
  text "ENEPIG" at 13731,2550.64 h60
  text "SURFACE FINISH:" at 11332.46,2549.64 h60
  text "X" at 12206.51,2549.64 h60
  text "IMM. TIN/SILVER OR EQUIV" at 11662,2392.64 h60
  text "OTHER" at 13093.46,2392.64 h60
  text "ARRAY/PANEL:" at 11332.46,2213.64 h60
  text "CUT AND TRIM PER MECH LAYER 1" at 12393.46,2209.35 h60
  text "N.C. ROUTE" at 12393.46,2057.64 h60
  text "X" at 13072.46,2057.64 h60
  text "V. SCORE" at 13259.46,2057.64 h60
  text "CERTIFICATION:" at 11332.46,1920.64 h60
  text "MATERIALS AND WORKMANSHIP FOR ALL PCBS" at 12057.46,1920.64 h60
  text "TO MEET OR EXCEED THE REQUIREMENTS OF:" at 12057.46,1822.64 h60
  text "X" at 11683.96,1686.13 h60
  text "ANSI IPC-A-600F CLASS ->" at 11822.96,1686.13 h60
  text "X" at 13462.02,1686.13 h60
  text "2" at 13580.96,1686.14 h60
  text "1" at 13265.96,1684.64 h60
  text "3" at 13934.96,1684.64 h60
  text "X" at 11686.02,1526.64 h60
  text "UL 94V-0" at 11822.96,1526.64 h60
  text "X" at 12498.02,1526.64 h60
  text "RoHS" at 12634.96,1526.64 h60
  text "OTHER" at 13279.36,1526.64 h60
  text "PER ORDER" at 13676.42,1526.64 h60
  text "ADDITIONAL REQUIREMENTS:" at 11332.46,1385.64 h60
  text "MICROSECTION:" at 11407.23,1270.64 h60
  text "YES" at 12312.96,1270.64 h60
  text "REQUIRED" at 13174.46,1114.49 h60
  text "BARE BOARD ELEC. TEST:" at 11407.23,1111.64 h60
  text "NONE" at 12712.96,1111.64 h60
  text "X" at 13047.46,1111.64 h60
  text "PER ORDER" at 13766.46,1111.64 h60
  text "MANUFACTURER'S UL:" at 11407.23,954.64 h60
  text "RAIL" at 12572.96,950.35 h60
  text "METAL" at 13064.77,950.35 h60
  text "X" at 13440,950 h60
  text "SILK" at 13576.46,950.35 h60
  text ".Layer_Name" at 577,-858.49 h60
M11 Gerber Information:
  lines w10: 3440,-726.83 3440,-523.5 ; -292,-1133.5 -292,-523.5 -292,-1133.5 ; -292,-1133.5 3713,-1133.5 ; -292,-1133.5 3713,-1133.5 ; -291.5,-1133.5 1284,-1133.5 -291.5,-1133.5 ; -291.5,-1133.5 -291.5,-523.5 ; -291.5,-1133.5 -291.5,-523.5 ; -291.5,-523.5 6310,-523.5 ; -291.5,-523.5 6310,-523.5 ; 3713,-1133.5 6310,-1133.5 ; 3713,-1133.5 6310,-1133.5 ; 6310,-1133.5 6310,-523.5 ; 6310,-1133.5 6310,-523.5 ; -292,-930.17 6308,-930.17 -292,-930.17 ; -292,-726.83 6310,-726.83 -292,-726.83 ; 2173,-1133.5 2173,-523.5 2173,-1133.5 ; 4280,-726.83 4280,-523.5 4280,-726.83 ; 4902,-1140 4902,-937.17 4902,-1140
  text "ALL ARTWORK VIEWED FROM TOP SIDE" at -228.5,-655.67 h60
  text "BOARD #:" at 2248,-655.67 h60
  text ".PRJ_Number" at 2793.5,-655.67 h60
  text "REV:" at 3638,-655.67 h60
  text ".PCB_Rev" at 3929.5,-655.67 h60
  text "SVN REV:" at 4476,-655.67 h60
  text "LAYER NAME =" at -228.5,-858.49 h60
  text "TID #:" at 2248,-859 h60
  text ".TID" at 2793.5,-859 h60
  text "PLOT NAME =" at -228.5,-1064.34 h60
  text ".plot_File_Name" at 577,-1064.34 h60
  text "GENERATED    :" at 2250,-1064.34 h60
  text ".Print_Date" at 3119.5,-1064.34 h60
  text ".Print_Time" at 3848.5,-1064.34 h60
  text "TEXAS INSTRUMENTS" at 5113,-1064.34 h60
M12 Stackup:
  drawing of 191 lines, arcs and shapes, not listed
  text "Layer" at 9790.34,7830 h60
  text "Name" at 10200.26,7830 h60
  text "Material" at 11130,7830 h60
  text "Thickness" at 11989.77,7830 h60
  text "Constant" at 12639.6,7830 h60
  text "Board Layer Stack" at 13209.46,7830 h60
  text "1" at 9790.34,7710 h60
  text "Top Overlay" at 10200.26,7710 h60
  text "2" at 9790.34,7590 h60
  text "Top Solder" at 10200.26,7590 h60
  text "Solder Resist" at 11130,7590 h60
  text "0.40mil" at 11989.77,7590 h60
  text "3.5" at 12639.6,7590 h60
  text "3" at 9790.34,7470 h60
  text "Top Layer" at 10200.26,7470 h60
  text "Copper" at 11130,7470 h60
  text "1.40mil" at 11989.77,7470 h60
  text "4" at 9790.34,7350 h60
  text "Dielectric1" at 10200.26,7350 h60
  text "FR-4" at 11130,7350 h60
  text "59.20mil" at 11989.77,7350 h60
  text "4.8" at 12639.6,7350 h60
  text "5" at 9790.34,7230 h60
  text "Bottom Layer" at 10200.26,7230 h60
  text "Copper" at 11130,7230 h60
  text "1.40mil" at 11989.77,7230 h60
  text "6" at 9790.34,7110 h60
  text "Bottom Solder" at 10200.26,7110 h60
  text "Solder Resist" at 11130,7110 h60
  text "0.40mil" at 11989.77,7110 h60
  text "3.5" at 12639.6,7110 h60
  text "7" at 9790.34,6990 h60
  text "Bottom Overlay" at 10200.26,6990 h60
  text ".Layer_Name" at 577,-858.49 h60
M13 Component Bodies Top:
  text ".Layer_Name" at 577,-858.49 h60
M14 Component Bodies Bottom:
  text ".Layer_Name" at 577,-858.49 h60
M15 Courtyards Top:
  text ".Layer_Name" at 577,-858.49 h60
M16 Courtyards Bottom:
  text ".Layer_Name" at 577,-858.49 h60
Drill Drawing:
  text ".Layer_Name" at 577,-858.49 h60

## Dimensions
0,-400 to 1000,-400 on M2 Board Dimensions
0,5800 to 8000,5800 on M2 Board Dimensions
8000,5800 to 8000,0 on M2 Board Dimensions
4000,5300 to 0,5800 on M2 Board Dimensions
